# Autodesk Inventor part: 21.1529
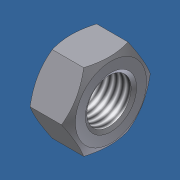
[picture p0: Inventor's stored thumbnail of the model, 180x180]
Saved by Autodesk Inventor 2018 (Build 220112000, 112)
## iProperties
Created: 2006-02
Part Number: 21.1529
Material: Steel, Mild
Description: M16 HEX NUT
Document SubType Name: Modeling
Standard: DIN 934
Designer: Andy Moles
Standards Organization: DIN
Language: en-US
Size Designation: M16
Categories: <MemberInstance><Categories><Category DisplayName="Fasteners" InternalName="e4da775c-781d-43d5-af7c-5136215cf5a6" Mnemonic="FSTN"><Category DisplayName="Nuts" I
Density: 7.85 g/cm^3
Mass: 34.4371 g
Surface Area: 21.9132 cm^2
Volume: 4.38689 cm^3
Appearance: Zinc
Author: Andy Moles
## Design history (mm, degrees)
sketch "Sketch1"
  geometry: L1 (-13.856, 0)-(-6.928, 12); L2 (-6.928, 12)-(6.928, 12); L3 (6.928, 12)-(13.856, 0); L4 (13.856, 0)-(6.928, -12); L5 (6.928, -12)-(-6.928, -12); L6 (-6.928, -12)-(-13.856, 0); 2 further points
  constraints: 12 end point, 1 coincident, 1 horizontal, 11 other
  dimensions: "d0" = 27.71281 distance of L3.end L1.start (= 1.1547 x SW)
extrude "Body" new body sketch "Sketch1" distance "d1" = 13 (= KOH); taper "d2" = 0 deg
sketch "Sketch2"
  geometry: L1 (0, 6.928)-(0, 13.856) reference; L2 (0, 13.856)-(13, 13.856) reference; L3 (13, 6.928)-(13, 13.856) reference; L4 (-1.3, 0)-(16.9, 0) reference; L5 (1.591, 13.856)-(0, 11.1); L6 (11.409, 13.856)-(13, 11.1)
  constraints: 4 end point, 4 point on line
  dimensions: "d3" = 30 deg angle of L1 L5 (= ANG1); "d4" = 30 deg angle of L3 L6 (= ANG2); "d5" = 22.2 diameter of L5.end L4 (= SW0); "d6" = 22.2 diameter of L6.end L4 (= SW01)
revolve "Chamfer1" sketch "Sketch2" stored, may be unused: angle "d7" = 90 deg
sketch "Sketch3"
  geometry: 4 further points
  constraints: 1 coincident, 1 other
hole "Thread" sketch "Sketch3" at (0, 0) diameter "d25" = 13.835; stored, may be unused: countersink angle "d29" = 82 deg, drill point angle "d31" = 118 deg; dims "d26" = 6, "d27" = 4, "d28" = 2, "d30" = 8
workaxis "Work Axis1"
workplane "Work Plane1"
body "Solid1"
chamfer "Chamfer2" distance "d8" = 1.08253 (= -0.5 x GD1 + 0.5 x NND); stored, may be unused: angle "d9" = 30 deg, second distance "d40" = 1.08253 (= -0.5 x GD1 + 0.5 x NND)
chamfer "Chamfer3" distance "d10" = 1.08253 (= -0.5 x GD1 + 0.5 x NND); stored, may be unused: angle "d11" = 30 deg, second distance "d41" = 1.08253 (= -0.5 x GD1 + 0.5 x NND)
other parameters: "ANG1" = 30 deg [user parameter; used in 1 equation term], "ANG2" = 30 deg [user parameter; used in 1 equation term], "NND" = 16 [user parameter; used in 4 equation terms], "KOH" = 13 [user parameter; used in 1 equation term], "SW" = 24 [user parameter; used in 2 equation terms], "SW0" = 22.2 (= SW01) [user parameter; used in 1 equation term], "SW01" = 22.2 [user parameter; used in 2 equation terms], "GD1" = 13.83494 (computed from THREADDIA, PTC, TOA) [user parameter; used in 4 equation terms], "d13" = 0, "d14" = 0, "d39" = 0, "d42" = 0, "GUL" = 1.08253 (= 0.541266 x PTC) [user parameter], "TPU" = 5 (computed from PTC) [user parameter], "THREADDIA" = 16 [user parameter; used in 1 equation term], "TOA" = 30 deg [user parameter; used in 1 equation term], "PTC" = 2 [user parameter; used in 4 equation terms], "E0" = 27.72 (= 1.155 x SW) [user parameter], "GAL" = 1.08253 (= 0.541266 x PTC) [user parameter]
